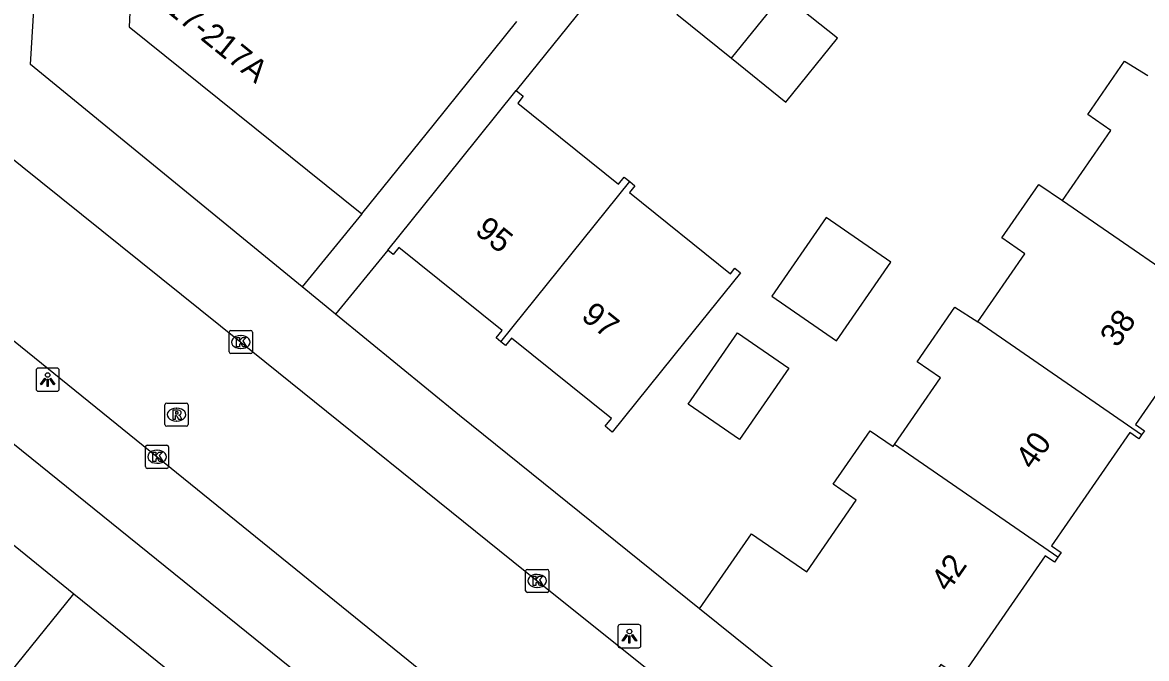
# Model space of a CAD drawing. Extents: x 160158 to 160921, y 381517 to 382041.
# Drawn here: x 160559.34 to 160607.85, y 381693.92 to 381721.4 of the extents above; entities that cross this region are included whole.
import ezdxf

# ---------------------------------------------------------------- set-up
doc = ezdxf.new("R2010")
doc.units = 0
for name, color, linetype in [('IMGEO_Kolk', 7, 'Continuous'), ('IMGEO_Lichtpunt', 7, 'Continuous'), ('IMGEO_Pand', 7, 'Continuous'), ('IMGEO_Pand_nummerreeks', 7, 'Continuous'), ('IMGEO_Rijbaan_lokaal_open', 7, 'Continuous'), ('IMGEO_Rioolput', 7, 'Continuous'), ('IMGEO_Voetpad_open', 7, 'Continuous')]:
    doc.layers.add(name, color=color, linetype=linetype)

msp = doc.modelspace()

# ---------------------------------------------------------------- linework, layer by layer
at = {"layer": 'IMGEO_Kolk'}
for p, q in [((160568.257, 381707.165), (160568.257, 381708.017)), ((160568.332, 381708.091), (160569.184, 381708.091)), ((160569.258, 381708.017), (160569.258, 381707.165)), ((160568.745, 381707.871), (160568.77, 381707.871)), ((160569.184, 381707.091), (160568.332, 381707.091)), ((160568.768, 381707.311), (160568.743, 381707.311)), ((160564.719, 381703.137), (160565.571, 381703.137)), ((160564.644, 381702.211), (160564.644, 381703.063)), ((160565.132, 381702.917), (160565.157, 381702.917)), ((160565.645, 381703.063), (160565.645, 381702.211)), ((160565.571, 381702.137), (160564.719, 381702.137)), ((160565.155, 381702.357), (160565.13, 381702.357)), ((160581.127, 381697.774), (160581.979, 381697.774)), ((160581.052, 381696.848), (160581.052, 381697.7)), ((160581.54, 381697.554), (160581.565, 381697.554)), ((160582.053, 381697.7), (160582.053, 381696.848)), ((160581.563, 381696.994), (160581.538, 381696.994)), ((160581.979, 381696.774), (160581.127, 381696.774))]:
    msp.add_line(p, q, dxfattribs=at)
for points in [[(160568.257, 381707.165), (160568.257, 381708.017)], [(160568.332, 381708.091), (160569.184, 381708.091)], [(160569.258, 381708.017), (160569.258, 381707.165)], [(160568.578, 381707.791), (160568.701, 381707.791), (160568.701, 381707.64), (160568.831, 381707.791), (160568.995, 381707.791), (160568.849, 381707.64), (160569.002, 381707.391), (160568.85, 381707.391), (160568.765, 381707.555), (160568.701, 381707.488), (160568.701, 381707.391), (160568.578, 381707.391), (160568.578, 381707.791)], [(160569.184, 381707.091), (160568.332, 381707.091)], [(160564.719, 381703.137), (160565.571, 381703.137)], [(160564.644, 381702.211), (160564.644, 381703.063)], [(160564.965, 381702.837), (160565.088, 381702.837), (160565.088, 381702.686), (160565.218, 381702.837), (160565.382, 381702.837), (160565.236, 381702.686), (160565.389, 381702.437), (160565.237, 381702.437), (160565.152, 381702.601), (160565.088, 381702.534), (160565.088, 381702.437), (160564.965, 381702.437), (160564.965, 381702.837)], [(160565.645, 381703.063), (160565.645, 381702.211)], [(160565.571, 381702.137), (160564.719, 381702.137)], [(160581.127, 381697.774), (160581.979, 381697.774)], [(160581.052, 381696.848), (160581.052, 381697.7)], [(160581.373, 381697.474), (160581.496, 381697.474), (160581.496, 381697.323), (160581.626, 381697.474), (160581.79, 381697.474), (160581.644, 381697.323), (160581.797, 381697.074), (160581.645, 381697.074), (160581.56, 381697.238), (160581.496, 381697.171), (160581.496, 381697.074), (160581.373, 381697.074), (160581.373, 381697.474)], [(160582.053, 381697.7), (160582.053, 381696.848)], [(160581.979, 381696.774), (160581.127, 381696.774)]]:
    msp.add_lwpolyline(points, dxfattribs=at)
for centre, start, end in [((160568.334, 381708.015), 91.552, 178.448), ((160568.334, 381708.015), 91.552, 178.448), ((160569.182, 381708.015), 1.552, 88.448), ((160569.182, 381708.015), 1.552, 88.448), ((160568.334, 381707.167), 181.552, 268.448), ((160568.334, 381707.167), 181.552, 268.448), ((160569.182, 381707.167), 271.552, 358.448), ((160569.182, 381707.167), 271.552, 358.448), ((160564.721, 381703.061), 91.552, 178.448), ((160564.721, 381703.061), 91.552, 178.448), ((160565.569, 381703.061), 1.552, 88.448), ((160565.569, 381703.061), 1.552, 88.448), ((160564.721, 381702.213), 181.552, 268.448), ((160564.721, 381702.213), 181.552, 268.448), ((160565.569, 381702.213), 271.552, 358.448), ((160565.569, 381702.213), 271.552, 358.448), ((160581.129, 381697.698), 91.552, 178.448), ((160581.129, 381697.698), 91.552, 178.448), ((160581.977, 381697.698), 1.552, 88.448), ((160581.977, 381697.698), 1.552, 88.448), ((160581.129, 381696.85), 181.552, 268.448), ((160581.129, 381696.85), 181.552, 268.448), ((160581.977, 381696.85), 271.552, 358.448), ((160581.977, 381696.85), 271.552, 358.448)]:
    msp.add_arc(centre, 0.0765, start, end, dxfattribs=at)
for centre, major_axis, ratio, start_param, end_param in [((160568.744, 381707.591), (-0.387, 0.002), 0.722429, 4.712389, 7.853982), ((160568.769, 381707.591), (-0.39, 0.002), 0.717154, 1.570796, 4.712389), ((160565.131, 381702.637), (-0.387, 0.002), 0.722429, 4.712389, 7.853982), ((160565.156, 381702.637), (-0.39, 0.002), 0.717154, 1.570796, 4.712389), ((160581.539, 381697.274), (-0.387, 0.002), 0.722429, 4.712389, 7.853982), ((160581.564, 381697.274), (-0.39, 0.002), 0.717154, 1.570796, 4.712389)]:
    msp.add_ellipse(centre, major_axis=major_axis, ratio=ratio, start_param=start_param, end_param=end_param, dxfattribs=at)
at = {"layer": 'IMGEO_Lichtpunt'}
for p, q in [((160559.926, 381706.371), (160559.926, 381705.564)), ((160559.926, 381706.371), (160559.926, 381705.564)), ((160560.828, 381706.466), (160560.02, 381706.466)), ((160560.828, 381706.466), (160560.02, 381706.466)), ((160560.922, 381705.564), (160560.922, 381706.371)), ((160560.922, 381705.564), (160560.922, 381706.371)), ((160560.02, 381705.47), (160560.828, 381705.47)), ((160560.02, 381705.47), (160560.828, 381705.47)), ((160585.934, 381695.387), (160585.126, 381695.387)), ((160585.934, 381695.387), (160585.126, 381695.387)), ((160585.032, 381695.292), (160585.032, 381694.485)), ((160585.032, 381695.292), (160585.032, 381694.485)), ((160586.028, 381694.485), (160586.028, 381695.292)), ((160586.028, 381694.485), (160586.028, 381695.292)), ((160585.126, 381694.391), (160585.934, 381694.391)), ((160585.126, 381694.391), (160585.934, 381694.391))]:
    msp.add_line(p, q, dxfattribs=at)
for points in [[(160560.3, 381706.035), (160560.339, 381706.007), (160560.151, 381705.745), (160560.113, 381705.772), (160560.3, 381706.035)], [(160560.512, 381706.007), (160560.55, 381706.034), (160560.737, 381705.772), (160560.698, 381705.744), (160560.512, 381706.007)], [(160560.402, 381705.987), (160560.449, 381705.987), (160560.449, 381705.665), (160560.402, 381705.665), (160560.402, 381705.987)], [(160585.406, 381694.956), (160585.445, 381694.928), (160585.257, 381694.666), (160585.219, 381694.693), (160585.406, 381694.956)], [(160585.508, 381694.908), (160585.555, 381694.908), (160585.555, 381694.586), (160585.508, 381694.586), (160585.508, 381694.908)], [(160585.618, 381694.928), (160585.656, 381694.955), (160585.843, 381694.693), (160585.804, 381694.665), (160585.618, 381694.928)]]:
    msp.add_lwpolyline(points, dxfattribs=at)
for centre in [(160560.425, 381706.169), (160585.531, 381695.09)]:
    msp.add_circle(centre, 0.0994, dxfattribs=at)
for centre, start, end in [((160560.02, 381706.371), 90, 180), ((160560.02, 381706.371), 90, 180), ((160560.828, 381706.371), 0, 90), ((160560.828, 381706.371), 0, 90), ((160560.02, 381705.564), 180, 270), ((160560.02, 381705.564), 180, 270), ((160560.828, 381705.564), 270, 0), ((160560.828, 381705.564), 270, 360), ((160585.126, 381695.292), 90, 180), ((160585.126, 381695.292), 90, 180), ((160585.934, 381695.292), 0, 90), ((160585.934, 381695.292), 0, 90), ((160585.126, 381694.485), 180, 270), ((160585.126, 381694.485), 180, 270), ((160585.934, 381694.485), 270, 0), ((160585.934, 381694.485), 270, 360)]:
    msp.add_arc(centre, 0.0946, start, end, dxfattribs=at)
at = {"layer": 'IMGEO_Pand'}
for points in [[(160564.183, 381726.487), (160563.936, 381721.212), (160573.979, 381713.128)], [(160592.15, 381722.608), (160589.796, 381724.503), (160587.578, 381721.747), (160589.931, 381719.852)], [(160589.931, 381719.852), (160592.15, 381722.608)], [(160589.931, 381719.852), (160592.285, 381717.957), (160594.504, 381720.713), (160592.15, 381722.608)], [(160573.979, 381713.128), (160577.115, 381717.023), (160580.671, 381721.44)], [(160604.225, 381713.711), (160606.31, 381716.73), (160605.312, 381717.419), (160606.899, 381719.717), (160607.906, 381719.099)], [(160575.103, 381711.563), (160578.239, 381715.458), (160580.648, 381718.45)], [(160580.648, 381718.45), (160580.949, 381718.208), (160580.709, 381717.911), (160585.058, 381714.41), (160585.305, 381714.716), (160585.548, 381714.52)], [(160585.548, 381714.52), (160585.769, 381714.342), (160585.535, 381714.051), (160589.893, 381710.543), (160590.081, 381710.777), (160590.328, 381710.577), (160587.927, 381707.594), (160584.791, 381703.699), (160584.477, 381703.952), (160584.753, 381704.296), (160580.444, 381707.765), (160580.186, 381707.444), (160579.982, 381707.608)], [(160579.982, 381707.608), (160585.548, 381714.52)], [(160600.567, 381708.468), (160602.593, 381711.402), (160601.601, 381712.087), (160603.199, 381714.402), (160604.225, 381713.711)], [(160604.225, 381713.711), (160611.283, 381708.839)], [(160591.675, 381709.568), (160594.46, 381707.643), (160596.807, 381711.041), (160594.022, 381712.965), (160591.675, 381709.568)], [(160579.982, 381707.608), (160579.782, 381707.769), (160580.041, 381708.091), (160575.586, 381711.678), (160575.34, 381711.372), (160575.103, 381711.563)], [(160596.966, 381703.161), (160598.956, 381706.042), (160597.946, 381706.74), (160599.571, 381709.092), (160600.567, 381708.468)], [(160607.635, 381703.589), (160600.567, 381708.468)], [(160611.283, 381708.839), (160611.133, 381708.621), (160610.736, 381708.894), (160607.375, 381704.027), (160607.755, 381703.764), (160607.635, 381703.589)], [(160590.28, 381703.382), (160588.07, 381704.909), (160590.201, 381707.994), (160592.411, 381706.467), (160590.28, 381703.382)], [(160588.56, 381696.072), (160590.799, 381699.315), (160593.183, 381697.668), (160595.32, 381700.762), (160594.323, 381701.451), (160595.918, 381703.761), (160596.908, 381703.077), (160596.966, 381703.161)], [(160607.635, 381703.589), (160607.514, 381703.414), (160607.123, 381703.685), (160603.744, 381698.793), (160604.161, 381698.505), (160604.016, 381698.295)], [(160604.016, 381698.295), (160596.966, 381703.161)], [(160556.409, 381700.887), (160561.559, 381696.713)], [(160604.016, 381698.295), (160603.87, 381698.084), (160603.467, 381698.363), (160600.014, 381693.364), (160600.403, 381693.096), (160600.209, 381692.815), (160599.82, 381693.084), (160598.975, 381693.667), (160596.32, 381689.825)], [(160555.44, 381689.163), (160561.559, 381696.713)], [(160561.559, 381696.713), (160566.569, 381692.651)], [(160596.32, 381689.825), (160588.56, 381696.072)]]:
    msp.add_lwpolyline(points, dxfattribs=at)
at = {"layer": 'IMGEO_Rijbaan_lokaal_open'}
for points in [[(160557.472, 381716.661), (160557.502, 381716.634), (160557.554, 381716.59), (160568.758, 381707.591), (160581.553, 381697.274), (160592.745, 381688.322), (160597.642, 381684.404), (160598.404, 381683.766)], [(160553.47, 381712.091), (160558.948, 381707.655), (160565.145, 381702.637), (160577.959, 381692.258), (160593.928, 381679.339), (160594.486, 381678.894)]]:
    msp.add_lwpolyline(points, dxfattribs=at)
at = {"layer": 'IMGEO_Rioolput'}
for p, q in [((160565.487, 381704.028), (160565.487, 381704.88)), ((160565.562, 381704.954), (160566.414, 381704.954)), ((160565.975, 381704.734), (160566, 381704.734)), ((160566.488, 381704.88), (160566.488, 381704.028)), ((160565.998, 381704.174), (160565.973, 381704.174)), ((160566.414, 381703.954), (160565.562, 381703.954))]:
    msp.add_line(p, q, dxfattribs=at)
for points in [[(160565.487, 381704.028), (160565.487, 381704.88)], [(160565.562, 381704.954), (160566.414, 381704.954)], [(160566.076, 381704.652), (160565.824, 381704.654), (160565.824, 381704.254)], [(160566.002, 381704.573), (160565.948, 381704.573), (160565.948, 381704.492)], [(160566.488, 381704.88), (160566.488, 381704.028)], [(160565.824, 381704.254), (160565.948, 381704.254), (160565.948, 381704.416), (160565.959, 381704.416)], [(160565.948, 381704.492), (160566, 381704.492)], [(160566.006, 381704.387), (160566.077, 381704.254), (160566.217, 381704.254), (160566.152, 381704.38)], [(160566.414, 381703.954), (160565.562, 381703.954)]]:
    msp.add_lwpolyline(points, dxfattribs=at)
for centre, radius, start, end in [((160565.564, 381704.878), 0.0765, 91.552, 178.448), ((160565.564, 381704.878), 0.0765, 91.552, 178.448), ((160566.008, 381704.477), 0.0964, 77.0061, 93.1865), ((160566.022, 381704.534), 0.0378, 276.6634, 79.6772), ((160566.075, 381704.542), 0.109, 350.3612, 89.416), ((160566.412, 381704.878), 0.0765, 1.552, 88.448), ((160566.412, 381704.878), 0.0765, 1.552, 88.448), ((160565.958, 381704.363), 0.0533, 26.0293, 88.6989), ((160565.984, 381704.681), 0.19, 274.7715, 282.9687), ((160566.073, 381704.542), 0.112, 277.5842, 350.9817), ((160566.057, 381704.327), 0.108, 29.5134, 73.7905), ((160565.564, 381704.03), 0.0765, 181.552, 268.448), ((160565.564, 381704.03), 0.0765, 181.552, 268.448), ((160566.412, 381704.03), 0.0765, 271.552, 358.448), ((160566.412, 381704.03), 0.0765, 271.552, 358.448)]:
    msp.add_arc(centre, radius, start, end, dxfattribs=at)
for centre, major_axis, ratio, start_param, end_param in [((160565.974, 381704.454), (-0.387, 0.002), 0.722429, 4.712389, 7.853982), ((160565.999, 381704.454), (-0.39, 0.002), 0.717154, 1.570796, 4.712389)]:
    msp.add_ellipse(centre, major_axis=major_axis, ratio=ratio, start_param=start_param, end_param=end_param, dxfattribs=at)
at = {"layer": 'IMGEO_Voetpad_open'}
for points in [[(160571.401, 381709.981), (160559.681, 381719.582), (160561.169, 381743.908)], [(160597.155, 381738.951), (160580.648, 381718.45)], [(160573.979, 381713.128), (160571.401, 381709.981)], [(160575.103, 381711.563), (160572.841, 381708.802)], [(160572.841, 381708.802), (160571.401, 381709.981)], [(160588.56, 381696.072), (160578.193, 381704.418), (160572.841, 381708.802)], [(160593.737, 381675.072), (160558.545, 381703.514), (160556.409, 381700.887)]]:
    msp.add_lwpolyline(points, dxfattribs=at)

# ---------------------------------------------------------------- texts
at = {"layer": 'IMGEO_Pand_nummerreeks'}
for s, rotation, p in [('217-217A', 321.1707, (160564.891, 381722.368)), ('95', 321.1562, (160578.816, 381712.313)), ('97', 321.1562, (160583.399, 381708.622)), ('38', 55.3565, (160606.587, 381707.311)), ('40', 55.3565, (160602.941, 381702.034)), ('42', 55.3565, (160599.292, 381696.753))]:
    msp.add_text(s, height=1, rotation=rotation, dxfattribs=at).set_placement(p)

doc.saveas('drawing.dxf')
